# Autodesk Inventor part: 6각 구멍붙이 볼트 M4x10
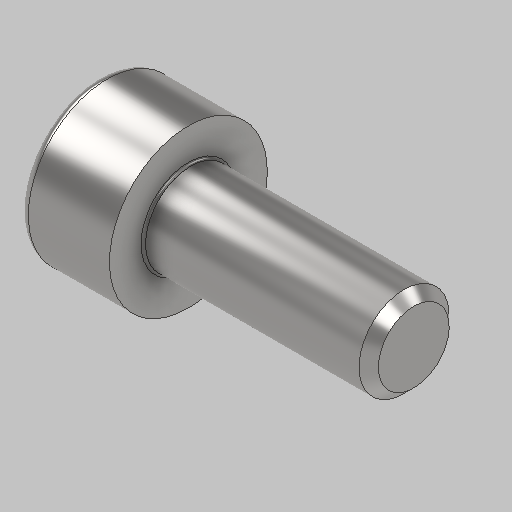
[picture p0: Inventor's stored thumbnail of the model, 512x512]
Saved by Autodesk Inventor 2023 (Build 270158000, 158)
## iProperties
Created: 2025-09
Part Number: 6각 구멍붙이 볼트 M4x10
Material: 강철, 연강
Description: 6각머리 태핑 나사
Document SubType Name: Modeling
Designer: home
Density: 7.85 g/cm^3
Appearance: 기본값
Author: jhkim
Sending System: Autodesk Inventor 2026
Preprocessor: ST-DEVELOPER v20.1
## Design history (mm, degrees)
feature "Solid1"
node "솔리드1"
